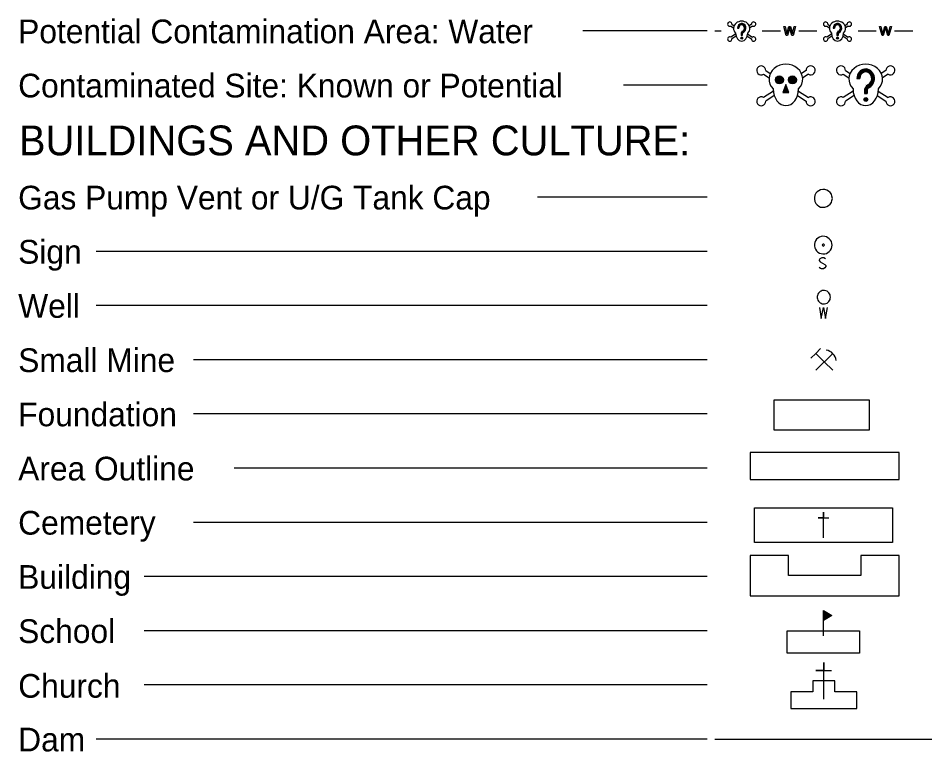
# Model space of a CAD drawing. Extents: x 2594871.4 to 2594905.1, y 784137.6 to 784159.6.
# Drawn here: x 2594875.39 to 2594882, y 784143.09 to 784148.4 of the extents above; entities that cross this region are included whole.
import ezdxf

# ---------------------------------------------------------------- set-up
doc = ezdxf.new("R2010")
doc.units = 0
doc.layers.add('Default', color=7, linetype='Continuous')

msp = doc.modelspace()

# ---------------------------------------------------------------- linework, layer by layer
at = {"layer": 'Default'}
for p, q in [((2594880.5487, 784148.3458), (2594880.5685, 784148.3334)), ((2594880.5565, 784148.3583), (2594880.5726, 784148.3482)), ((2594880.5966, 784148.3307), (2594880.606, 784148.3307)), ((2594880.6973, 784148.3583), (2594880.6813, 784148.3482)), ((2594880.7052, 784148.3458), (2594880.6854, 784148.3334)), ((2594881.2421, 784148.3458), (2594881.2619, 784148.3334)), ((2594881.2499, 784148.3583), (2594881.266, 784148.3482)), ((2594881.29, 784148.3307), (2594881.2994, 784148.3307)), ((2594881.3908, 784148.3583), (2594881.3747, 784148.3482)), ((2594881.3986, 784148.3458), (2594881.3788, 784148.3334)), ((2594880.3766, 784148.3099), (2594879.4786, 784148.3099)), ((2594880.433, 784148.3101), (2594880.4784, 784148.3101)), ((2594880.5832, 784148.2866), (2594880.5487, 784148.2649)), ((2594880.5866, 784148.2713), (2594880.5565, 784148.2524)), ((2594880.6223, 784148.2865), (2594880.6223, 784148.2782)), ((2594880.6223, 784148.2782), (2594880.6316, 784148.2782)), ((2594880.6236, 784148.2865), (2594880.6236, 784148.2782)), ((2594880.6249, 784148.2865), (2594880.6249, 784148.2782)), ((2594880.6263, 784148.2865), (2594880.6263, 784148.2782)), ((2594880.6269, 784148.3101), (2594880.6269, 784148.3101)), ((2594880.6276, 784148.2865), (2594880.6276, 784148.2782)), ((2594880.629, 784148.2865), (2594880.629, 784148.2782)), ((2594880.6303, 784148.2865), (2594880.6303, 784148.2782)), ((2594880.6316, 784148.2865), (2594880.6316, 784148.2782)), ((2594880.6673, 784148.2713), (2594880.6973, 784148.2524)), ((2594880.6706, 784148.2866), (2594880.7052, 784148.2649)), ((2594880.7755, 784148.3101), (2594880.9076, 784148.3101)), ((2594881.0397, 784148.3101), (2594881.1718, 784148.3101)), ((2594881.2766, 784148.2866), (2594881.2421, 784148.2649)), ((2594881.28, 784148.2713), (2594881.2499, 784148.2524)), ((2594881.3157, 784148.2865), (2594881.3157, 784148.2782)), ((2594881.3157, 784148.2782), (2594881.325, 784148.2782)), ((2594881.317, 784148.2865), (2594881.317, 784148.2782)), ((2594881.3183, 784148.2865), (2594881.3183, 784148.2782)), ((2594881.3197, 784148.2865), (2594881.3197, 784148.2782)), ((2594881.3203, 784148.3101), (2594881.3203, 784148.3101)), ((2594881.321, 784148.2865), (2594881.321, 784148.2782)), ((2594881.3224, 784148.2865), (2594881.3224, 784148.2782)), ((2594881.3237, 784148.2865), (2594881.3237, 784148.2782)), ((2594881.325, 784148.2865), (2594881.325, 784148.2782)), ((2594881.3607, 784148.2713), (2594881.3908, 784148.2524)), ((2594881.3641, 784148.2866), (2594881.3986, 784148.2649)), ((2594881.4689, 784148.3101), (2594881.601, 784148.3101)), ((2594881.7331, 784148.3101), (2594881.8652, 784148.3101)), ((2594880.7845, 784147.9968), (2594880.8256, 784147.9709)), ((2594880.8007, 784148.0227), (2594880.834, 784148.0017)), ((2594881.0935, 784148.0227), (2594881.0602, 784148.0017)), ((2594881.1098, 784147.9968), (2594881.0687, 784147.9709)), ((2594881.3617, 784147.9968), (2594881.4028, 784147.9709)), ((2594881.378, 784148.0227), (2594881.4113, 784148.0017)), ((2594881.6708, 784148.0227), (2594881.6375, 784148.0017)), ((2594881.6871, 784147.9968), (2594881.6459, 784147.9709)), ((2594880.3766, 784147.9176), (2594879.7717, 784147.9176)), ((2594881.4614, 784147.9652), (2594881.4808, 784147.9652)), ((2594881.5244, 784147.9226), (2594881.5244, 784147.9226)), ((2594880.8563, 784147.8736), (2594880.7845, 784147.8284)), ((2594880.9471, 784147.9126), (2594880.9471, 784147.9126)), ((2594881.038, 784147.8736), (2594881.1098, 784147.8284)), ((2594881.4335, 784147.8736), (2594881.3617, 784147.8284)), ((2594881.5147, 784147.8733), (2594881.5147, 784147.8562)), ((2594881.5147, 784147.8562), (2594881.5341, 784147.8562)), ((2594881.5174, 784147.8733), (2594881.5174, 784147.8562)), ((2594881.5202, 784147.8733), (2594881.5202, 784147.8562)), ((2594881.523, 784147.8733), (2594881.523, 784147.8562)), ((2594881.5258, 784147.8733), (2594881.5258, 784147.8562)), ((2594881.5286, 784147.8733), (2594881.5286, 784147.8562)), ((2594881.5313, 784147.8733), (2594881.5313, 784147.8562)), ((2594881.5341, 784147.8733), (2594881.5341, 784147.8562)), ((2594881.6153, 784147.8736), (2594881.6871, 784147.8284)), ((2594880.8632, 784147.8418), (2594880.8007, 784147.8025)), ((2594881.0311, 784147.8418), (2594881.0935, 784147.8025)), ((2594881.4404, 784147.8418), (2594881.378, 784147.8025)), ((2594881.6083, 784147.8418), (2594881.6708, 784147.8025)), ((2594880.3766, 784147.1066), (2594879.149, 784147.1066)), ((2594880.3766, 784146.7143), (2594875.9548, 784146.7143)), ((2594880.3766, 784146.322), (2594875.9548, 784146.322)), ((2594881.1635, 784145.976), (2594881.1281, 784145.9405)), ((2594881.1635, 784145.8539), (2594881.2856, 784145.976)), ((2594880.3766, 784145.9297), (2594876.661, 784145.9297)), ((2594881.2246, 784145.9149), (2594881.2177, 784145.9218)), ((2594881.2246, 784145.9149), (2594881.2856, 784145.8539)), ((2594880.8629, 784145.6401), (2594881.5494, 784145.6401)), ((2594880.8629, 784145.4207), (2594880.8629, 784145.6401)), ((2594881.5494, 784145.6401), (2594881.5494, 784145.4207)), ((2594880.3766, 784145.5374), (2594876.661, 784145.5374)), ((2594881.5494, 784145.4207), (2594880.8629, 784145.4207)), ((2594881.7666, 784145.2588), (2594880.6878, 784145.2588)), ((2594880.6878, 784145.2588), (2594880.6878, 784145.0627)), ((2594881.7666, 784145.0627), (2594881.7666, 784145.2588)), ((2594880.3766, 784145.1451), (2594876.9542, 784145.1451)), ((2594880.6878, 784145.0627), (2594881.7666, 784145.0627)), ((2594880.7202, 784144.8592), (2594881.7179, 784144.8592)), ((2594880.7202, 784144.6081), (2594880.7202, 784144.8592)), ((2594881.7179, 784144.8592), (2594881.7179, 784144.6081)), ((2594880.3766, 784144.7528), (2594876.661, 784144.7528)), ((2594881.7179, 784144.6081), (2594880.7202, 784144.6081)), ((2594880.9656, 784144.5142), (2594880.6878, 784144.5142)), ((2594880.6878, 784144.5142), (2594880.6878, 784144.2199)), ((2594880.9656, 784144.3671), (2594880.9656, 784144.5142)), ((2594881.7666, 784144.5142), (2594881.4888, 784144.5142)), ((2594881.4888, 784144.5142), (2594881.4888, 784144.3671)), ((2594881.7666, 784144.2199), (2594881.7666, 784144.5142)), ((2594880.3766, 784144.3604), (2594876.3023, 784144.3604)), ((2594881.4888, 784144.3671), (2594880.9656, 784144.3671)), ((2594880.6878, 784144.2199), (2594881.7666, 784144.2199)), ((2594880.3766, 784143.9681), (2594876.3023, 784143.9681)), ((2594880.956, 784143.9681), (2594881.4803, 784143.9681)), ((2594880.956, 784143.8053), (2594880.956, 784143.9681)), ((2594881.4803, 784143.9681), (2594881.4803, 784143.8053)), ((2594881.4803, 784143.8053), (2594880.956, 784143.8053)), ((2594880.3766, 784143.5758), (2594876.3023, 784143.5758)), ((2594881.3003, 784143.605), (2594881.1414, 784143.605)), ((2594881.1414, 784143.605), (2594881.1414, 784143.5258)), ((2594881.3003, 784143.5258), (2594881.3003, 784143.605)), ((2594881.1414, 784143.5258), (2594880.9825, 784143.5258)), ((2594880.9825, 784143.5258), (2594880.9825, 784143.4064)), ((2594881.4592, 784143.5258), (2594881.3003, 784143.5258)), ((2594881.4592, 784143.4064), (2594881.4592, 784143.5258)), ((2594880.9825, 784143.4064), (2594881.4592, 784143.4064)), ((2594880.3766, 784143.1835), (2594875.9548, 784143.1835)), ((2594880.433, 784143.1835), (2594882.0023, 784143.1835))]:
    msp.add_line(p, q, dxfattribs=at)
for points in [[(2594880.9722, 784148.3275), (2594880.9583, 784148.2771), (2594880.9493, 784148.2771), (2594880.9317, 784148.3432), (2594880.9407, 784148.3432), (2594880.9508, 784148.2999)], [(2594880.9565, 784148.2986), (2594880.9691, 784148.3432), (2594880.9796, 784148.3432), (2594880.9891, 784148.3097)], [(2594880.9975, 784148.3007), (2594881.0079, 784148.3432), (2594881.0167, 784148.3432), (2594880.9986, 784148.2771), (2594880.9901, 784148.2771), (2594880.9763, 784148.3275)], [(2594881.6656, 784148.3275), (2594881.6517, 784148.2771), (2594881.6427, 784148.2771), (2594881.6251, 784148.3432), (2594881.6341, 784148.3432), (2594881.6442, 784148.2999)], [(2594881.6499, 784148.2986), (2594881.6625, 784148.3432), (2594881.6731, 784148.3432), (2594881.6825, 784148.3097)], [(2594881.6909, 784148.3007), (2594881.7013, 784148.3432), (2594881.7101, 784148.3432), (2594881.692, 784148.2771), (2594881.6835, 784148.2771), (2594881.6697, 784148.3275)], [(2594881.2835, 784147.0983), (2594881.28, 784147.1139), (2594881.2765, 784147.1278), (2594881.2678, 784147.14), (2594881.2556, 784147.1504), (2594881.2435, 784147.1574), (2594881.2296, 784147.1626), (2594881.2139, 784147.1626), (2594881.1983, 784147.1608), (2594881.1844, 784147.1539), (2594881.1722, 784147.1452), (2594881.1636, 784147.1347), (2594881.1566, 784147.1208), (2594881.1531, 784147.1052), (2594881.1531, 784147.0913), (2594881.1566, 784147.0757), (2594881.1636, 784147.0618), (2594881.1722, 784147.0513), (2594881.1844, 784147.0427), (2594881.1983, 784147.0357), (2594881.2139, 784147.0339), (2594881.2296, 784147.0339), (2594881.2435, 784147.0392), (2594881.2556, 784147.0462), (2594881.2678, 784147.0566), (2594881.2765, 784147.0687), (2594881.28, 784147.0826), (2594881.2835, 784147.0983)], [(2594881.2816, 784146.7599), (2594881.2803, 784146.7726), (2594881.2765, 784146.7853), (2594881.2701, 784146.7968), (2594881.2612, 784146.8057), (2594881.2511, 784146.8134), (2594881.2396, 784146.8198), (2594881.2281, 784146.8223), (2594881.2141, 784146.8236), (2594881.2014, 784146.821), (2594881.1899, 784146.8172), (2594881.1784, 784146.8108), (2594881.1695, 784146.8019), (2594881.1618, 784146.7904), (2594881.1567, 784146.7789), (2594881.1542, 784146.7662), (2594881.1542, 784146.7535), (2594881.1567, 784146.7407), (2594881.1618, 784146.7293), (2594881.1695, 784146.7178), (2594881.1784, 784146.7089), (2594881.1899, 784146.7025), (2594881.2014, 784146.6987), (2594881.2141, 784146.6961), (2594881.2281, 784146.6974), (2594881.2396, 784146.7), (2594881.2511, 784146.7063), (2594881.2612, 784146.714), (2594881.2701, 784146.7229), (2594881.2765, 784146.7344), (2594881.2803, 784146.7471), (2594881.2816, 784146.7599)], [(2594881.2205, 784146.7675), (2594881.2166, 784146.7675), (2594881.2128, 784146.765), (2594881.2103, 784146.7611), (2594881.2115, 784146.7573), (2594881.2141, 784146.7535), (2594881.2179, 784146.7522), (2594881.2217, 784146.7535), (2594881.2243, 784146.756), (2594881.2255, 784146.7611), (2594881.2243, 784146.765), (2594881.2205, 784146.7675)], [(2594881.2328, 784146.6617), (2594881.2205, 784146.6672), (2594881.2063, 784146.6672), (2594881.1933, 784146.6617), (2594881.1877, 784146.6518), (2594881.1877, 784146.6481), (2594881.1939, 784146.6388), (2594881.2298, 784146.6203), (2594881.2359, 784146.6116), (2594881.2353, 784146.6042), (2594881.2298, 784146.5943), (2594881.2193, 784146.5888), (2594881.2044, 784146.5888), (2594881.1976, 784146.5912), (2594881.1877, 784146.598)], [(2594881.2698, 784146.383), (2594881.2683, 784146.3915), (2594881.2668, 784146.4), (2594881.2629, 784146.4077), (2594881.2575, 784146.4146), (2594881.2513, 784146.4208), (2594881.2444, 784146.4255), (2594881.2359, 784146.4285), (2594881.2274, 784146.4308), (2594881.2189, 784146.4308), (2594881.2104, 784146.4301), (2594881.2019, 784146.427), (2594881.195, 784146.4231), (2594881.188, 784146.4177), (2594881.1818, 784146.4115), (2594881.1779, 784146.4038), (2594881.1749, 784146.3961), (2594881.1733, 784146.3876), (2594881.1733, 784146.3783), (2594881.1749, 784146.3698), (2594881.1779, 784146.3621), (2594881.1818, 784146.3544), (2594881.188, 784146.3482), (2594881.195, 784146.3428), (2594881.2019, 784146.3389), (2594881.2104, 784146.3359), (2594881.2189, 784146.3351), (2594881.2274, 784146.3351), (2594881.2359, 784146.3374), (2594881.2444, 784146.3405), (2594881.2513, 784146.3451), (2594881.2575, 784146.3513), (2594881.2629, 784146.3582), (2594881.2668, 784146.366), (2594881.2683, 784146.3745), (2594881.2698, 784146.383)], [(2594881.1897, 784146.3073), (2594881.2021, 784146.2288), (2594881.2181, 784146.3073), (2594881.2342, 784146.2288), (2594881.2478, 784146.3073)], [(2594881.2246, 784145.9149), (2594881.1635, 784145.976), (2594881.198, 784146.0104)], [(2594881.3102, 784145.9257), (2594881.3073, 784145.9395), (2594881.3023, 784145.9523), (2594881.2954, 784145.9641), (2594881.2866, 784145.974), (2594881.2767, 784145.9838), (2594881.2649, 784145.9907), (2594881.2521, 784145.9966), (2594881.2393, 784145.9996)], [(2594881.2194, 784144.6419), (2594881.2194, 784144.8258), (2594881.2194, 784144.7867), (2594881.1803, 784144.7867), (2594881.2585, 784144.7867)], [(2594881.2189, 784143.9316), (2594881.2189, 784144.1155), (2594881.2804, 784144.0793), (2594881.2189, 784144.0431), (2594881.2225, 784144.0489), (2594881.2225, 784144.1104), (2594881.2732, 784144.0786), (2594881.2261, 784144.0511), (2594881.2269, 784144.1046), (2594881.2674, 784144.0786), (2594881.2305, 784144.0576), (2594881.2305, 784144.0981), (2594881.2609, 784144.0786), (2594881.2348, 784144.0641), (2594881.2348, 784144.0916), (2594881.2544, 784144.0793), (2594881.2384, 784144.0699), (2594881.2384, 784144.0851), (2594881.2486, 784144.0793), (2594881.2421, 784144.0757), (2594881.2413, 784144.08), (2594881.2435, 784144.0793)], [(2594881.2208, 784143.4726), (2594881.2208, 784143.7374), (2594881.2208, 784143.6811), (2594881.1645, 784143.6811), (2594881.2772, 784143.6811)]]:
    msp.add_lwpolyline(points, dxfattribs=at)
for points in [[(2594880.9471, 784147.9226), (2594880.9256, 784147.8638), (2594880.9686, 784147.8638)], [(2594880.9471, 784147.9126), (2594880.9305, 784147.8672), (2594880.9637, 784147.8672)], [(2594880.9471, 784147.9026), (2594880.9354, 784147.8707), (2594880.9588, 784147.8707)], [(2594880.9471, 784147.8926), (2594880.9404, 784147.8741), (2594880.9539, 784147.8741)], [(2594880.9471, 784147.8826), (2594880.9453, 784147.8775), (2594880.949, 784147.8775)]]:
    msp.add_lwpolyline(points, close=True, dxfattribs=at)
for centre, radius in [((2594880.6273, 784148.2579), 0.00669), ((2594880.6273, 784148.2579), 0.0052), ((2594880.6273, 784148.2579), 0.00368), ((2594880.6273, 784148.2579), 0.0022), ((2594880.6273, 784148.2579), 0.000713), ((2594881.3207, 784148.2579), 0.00669), ((2594881.3207, 784148.2579), 0.0052), ((2594881.3207, 784148.2579), 0.00368), ((2594881.3207, 784148.2579), 0.0022), ((2594881.3207, 784148.2579), 0.000713), ((2594880.8998, 784147.956), 0.0291), ((2594880.9944, 784147.956), 0.0291), ((2594880.8998, 784147.956), 0.0257), ((2594880.8998, 784147.956), 0.0222), ((2594880.8998, 784147.956), 0.0188), ((2594880.8998, 784147.956), 0.0154), ((2594880.8998, 784147.956), 0.0119), ((2594880.8998, 784147.956), 0.00851), ((2594880.8998, 784147.956), 0.00508), ((2594880.8998, 784147.956), 0.00165), ((2594880.9944, 784147.956), 0.0257), ((2594880.9944, 784147.956), 0.0222), ((2594880.9944, 784147.956), 0.0188), ((2594880.9944, 784147.956), 0.0154), ((2594880.9944, 784147.956), 0.0119), ((2594880.9944, 784147.956), 0.00851), ((2594880.9944, 784147.956), 0.00508), ((2594880.9944, 784147.956), 0.00165), ((2594881.5251, 784147.8139), 0.0139), ((2594881.5251, 784147.8139), 0.0108), ((2594881.5251, 784147.8139), 0.00766), ((2594881.5251, 784147.8139), 0.00457), ((2594881.5251, 784147.8139), 0.00148)]:
    msp.add_circle(centre, radius, dxfattribs=at)
for centre, radius, start, end in [((2594880.5409, 784148.3594), 0.0157, 355.89762, 299.80617), ((2594880.713, 784148.3594), 0.0157, 240.19383, 184.10238), ((2594881.2343, 784148.3594), 0.0157, 355.89762, 299.80617), ((2594881.4064, 784148.3594), 0.0157, 240.19383, 184.10238), ((2594880.5409, 784148.2513), 0.0157, 60.19383, 4.10238), ((2594880.713, 784148.2513), 0.0157, 175.89762, 119.80617), ((2594881.2343, 784148.2513), 0.0157, 60.19383, 4.10238), ((2594881.4064, 784148.2513), 0.0157, 175.89762, 119.80617), ((2594880.7683, 784148.025), 0.0325, 355.89762, 299.80617), ((2594881.126, 784148.025), 0.0325, 240.19383, 184.10238), ((2594881.3455, 784148.025), 0.0325, 355.89762, 299.80617), ((2594881.7032, 784148.025), 0.0325, 240.19383, 184.10238), ((2594880.7683, 784147.8002), 0.0325, 60.19383, 4.10238), ((2594881.126, 784147.8002), 0.0325, 175.89762, 119.80617), ((2594881.3455, 784147.8002), 0.0325, 60.19383, 4.10238), ((2594881.7032, 784147.8002), 0.0325, 175.89762, 119.80617)]:
    msp.add_arc(centre, radius, start, end, dxfattribs=at)
for centre, major_axis, ratio, start_param, end_param in [((2594880.6269, 784148.3287), (0.0587, 0), 0.885014, 5.564242, 10.143721), ((2594881.3203, 784148.3287), (0.0587, 0), 0.885014, 5.564242, 10.143721), ((2594880.6269, 784148.3307), (0, 0.0337), 0.9, 3.567618, 7.853982), ((2594880.6269, 784148.3307), (0, 0.0322), 0.9, 3.567618, 7.853982), ((2594880.6269, 784148.3307), (0, 0.0307), 0.9, 3.567618, 7.853982), ((2594880.6269, 784148.3307), (0, 0.0292), 0.9, 3.567618, 7.853982), ((2594880.6269, 784148.3307), (0, 0.0277), 0.9, 3.567618, 7.853982), ((2594880.6269, 784148.3307), (0, 0.0263), 0.9, 3.567618, 7.853982), ((2594880.6269, 784148.3307), (0, 0.0248), 0.9, 3.567618, 7.853982), ((2594880.6269, 784148.3307), (0, 0.0233), 0.9, 3.567618, 7.853982), ((2594881.3203, 784148.3307), (0, 0.0337), 0.9, 3.567618, 7.853982), ((2594881.3203, 784148.3307), (0, 0.0322), 0.9, 3.567618, 7.853982), ((2594881.3203, 784148.3307), (0, 0.0307), 0.9, 3.567618, 7.853982), ((2594881.3203, 784148.3307), (0, 0.0292), 0.9, 3.567618, 7.853982), ((2594881.3203, 784148.3307), (0, 0.0277), 0.9, 3.567618, 7.853982), ((2594881.3203, 784148.3307), (0, 0.0263), 0.9, 3.567618, 7.853982), ((2594881.3203, 784148.3307), (0, 0.0248), 0.9, 3.567618, 7.853982), ((2594881.3203, 784148.3307), (0, 0.0233), 0.9, 3.567618, 7.853982), ((2594880.6269, 784148.2951), (0, -0.0587), 0.752542, 4.722735, 7.843636), ((2594880.645, 784148.2865), (0, 0.0253), 0.9, 0.426026, 1.570796), ((2594880.645, 784148.2865), (0, 0.0238), 0.9, 0.426026, 1.570796), ((2594880.645, 784148.2865), (0, 0.0223), 0.9, 0.426026, 1.570796), ((2594880.645, 784148.2865), (0, 0.0208), 0.9, 0.426026, 1.570796), ((2594880.645, 784148.2865), (0, 0.0193), 0.9, 0.426026, 1.570796), ((2594880.645, 784148.2865), (0, 0.0178), 0.9, 0.426026, 1.570796), ((2594880.645, 784148.2865), (0, 0.0163), 0.9, 0.426026, 1.570796), ((2594880.645, 784148.2865), (0, 0.0149), 0.9, 0.426026, 1.570796), ((2594881.3203, 784148.2951), (0, -0.0587), 0.752542, 4.722735, 7.843636), ((2594881.3384, 784148.2865), (0, 0.0253), 0.9, 0.426026, 1.570796), ((2594881.3384, 784148.2865), (0, 0.0238), 0.9, 0.426026, 1.570796), ((2594881.3384, 784148.2865), (0, 0.0223), 0.9, 0.426026, 1.570796), ((2594881.3384, 784148.2865), (0, 0.0208), 0.9, 0.426026, 1.570796), ((2594881.3384, 784148.2865), (0, 0.0193), 0.9, 0.426026, 1.570796), ((2594881.3384, 784148.2865), (0, 0.0178), 0.9, 0.426026, 1.570796), ((2594881.3384, 784148.2865), (0, 0.0163), 0.9, 0.426026, 1.570796), ((2594881.3384, 784148.2865), (0, 0.0149), 0.9, 0.426026, 1.570796), ((2594880.9471, 784147.9611), (0.122, 0), 0.885014, 5.564242, 10.143721), ((2594881.5244, 784147.9611), (0.122, 0), 0.885014, 5.564242, 10.143721), ((2594881.5244, 784147.9652), (0, 0.07), 0.9, 3.567618, 7.853982), ((2594881.5244, 784147.9652), (0, 0.0669), 0.9, 3.567618, 7.853982), ((2594881.5244, 784147.9652), (0, 0.0639), 0.9, 3.567618, 7.853982), ((2594881.5244, 784147.9652), (0, 0.0608), 0.9, 3.567618, 7.853982), ((2594881.5244, 784147.9652), (0, 0.0577), 0.9, 3.567618, 7.853982), ((2594881.5244, 784147.9652), (0, 0.0546), 0.9, 3.567618, 7.853982), ((2594881.5244, 784147.9652), (0, 0.0515), 0.9, 3.567618, 7.853982), ((2594881.5244, 784147.9652), (0, 0.0484), 0.9, 3.567618, 7.853982), ((2594881.5619, 784147.8733), (0, 0.0525), 0.9, 0.426026, 1.570796), ((2594881.5619, 784147.8733), (0, 0.0494), 0.9, 0.426026, 1.570796), ((2594880.9471, 784147.8913), (0, -0.122), 0.752542, 4.722735, 7.843636), ((2594881.5244, 784147.8913), (0, -0.122), 0.752542, 4.722735, 7.843636), ((2594881.5619, 784147.8733), (0, 0.0463), 0.9, 0.426026, 1.570796), ((2594881.5619, 784147.8733), (0, 0.0433), 0.9, 0.426026, 1.570796), ((2594881.5619, 784147.8733), (0, 0.0402), 0.9, 0.426026, 1.570796), ((2594881.5619, 784147.8733), (0, 0.0371), 0.9, 0.426026, 1.570796), ((2594881.5619, 784147.8733), (0, 0.034), 0.9, 0.426026, 1.570796), ((2594881.5619, 784147.8733), (0, 0.0309), 0.9, 0.426026, 1.570796)]:
    msp.add_ellipse(centre, major_axis=major_axis, ratio=ratio, start_param=start_param, end_param=end_param, dxfattribs=at)
for points in [[(2594880.9742, 784148.3352), (2594880.9731, 784148.3307), (2594880.9722, 784148.3275)], [(2594880.9763, 784148.3275), (2594880.9745, 784148.3338), (2594880.9742, 784148.3352)], [(2594881.6676, 784148.3352), (2594881.6665, 784148.3307), (2594881.6656, 784148.3275)], [(2594881.6697, 784148.3275), (2594881.6679, 784148.3338), (2594881.6676, 784148.3352)], [(2594880.9508, 784148.2999), (2594880.9524, 784148.2931), (2594880.9536, 784148.2864)], [(2594880.9536, 784148.2864), (2594880.9561, 784148.2969), (2594880.9565, 784148.2986)], [(2594880.9891, 784148.3097), (2594880.9926, 784148.2973), (2594880.9942, 784148.2864)], [(2594880.9942, 784148.2864), (2594880.9955, 784148.2926), (2594880.9975, 784148.3007)], [(2594881.6442, 784148.2999), (2594881.6458, 784148.2931), (2594881.647, 784148.2864)], [(2594881.647, 784148.2864), (2594881.6495, 784148.2969), (2594881.6499, 784148.2986)], [(2594881.6825, 784148.3097), (2594881.686, 784148.2973), (2594881.6876, 784148.2864)], [(2594881.6876, 784148.2864), (2594881.6889, 784148.2926), (2594881.6909, 784148.3007)]]:
    msp.add_open_spline(points, degree=2, dxfattribs=at)

# ---------------------------------------------------------------- texts
for s, height, p in [('Potential Contamination Area: Water', 0.171636, (2594875.3911, 784148.2211)), ('Contaminated Site: Known or Potential', 0.171636, (2594875.3911, 784147.8288)), ('BUILDINGS AND OTHER CULTURE:', 0.21577, (2594875.3965, 784147.4097)), ('Gas Pump Vent or U/G Tank Cap', 0.171636, (2594875.3911, 784147.0178)), ('Sign', 0.17164, (2594875.3914, 784146.6258)), ('Well', 0.17164, (2594875.3914, 784146.2335)), ('Small Mine', 0.17164, (2594875.3914, 784145.8409)), ('Foundation', 0.17164, (2594875.3914, 784145.4486)), ('Area Outline', 0.171636, (2594875.3914, 784145.0563)), ('Cemetery', 0.17164, (2594875.3911, 784144.6642)), ('Building', 0.17164, (2594875.3914, 784144.2719)), ('School', 0.17164, (2594875.3911, 784143.8796)), ('Church', 0.17164, (2594875.3916, 784143.4836)), ('Dam', 0.17164, (2594875.3914, 784143.095))]:
    msp.add_text(s, height=height, rotation=360, dxfattribs=at).set_placement(p)

doc.saveas('drawing.dxf')
